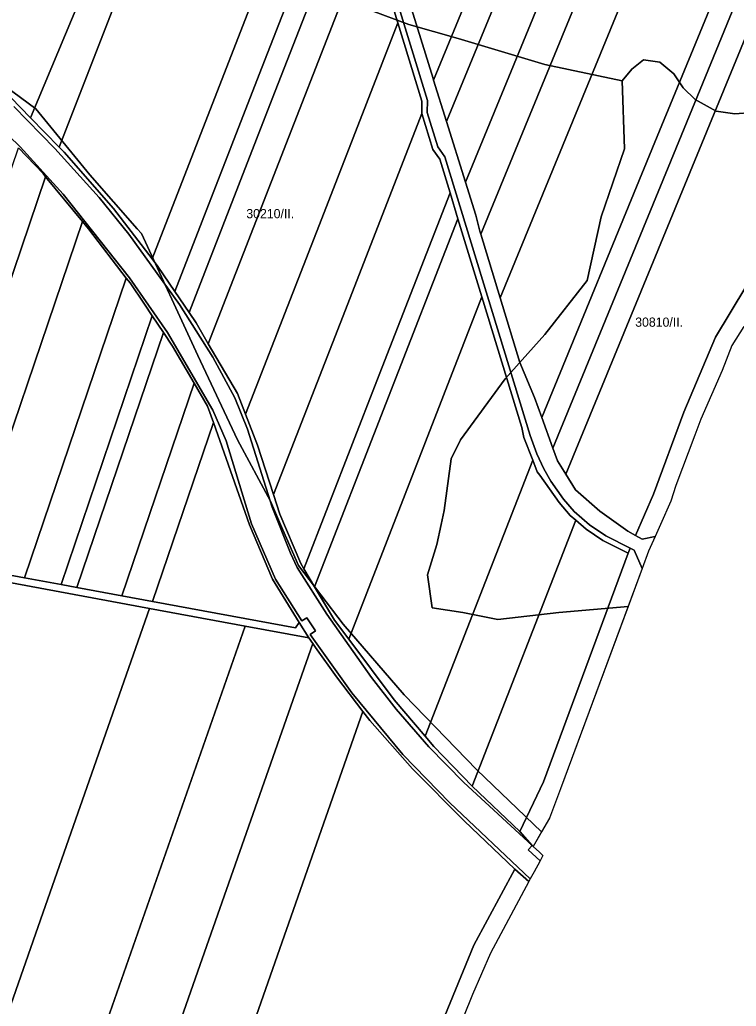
# Model space of a CAD drawing. Extents: x -545779 to -541342, y -1153413 to -1149956.
# Drawn here: x -543814 to -543424, y -1152262 to -1151726 of the extents above; entities that cross this region are included whole.
import ezdxf

# ---------------------------------------------------------------- set-up
doc = ezdxf.new("R2010")
doc.units = 0
for name, color, linetype in [('95560013', 7, 'Continuous'), ('95610013', 7, 'Continuous'), ('95640013', 7, 'Continuous'), ('95660013', 7, 'Continuous')]:
    doc.layers.add(name, color=color, linetype=linetype)

msp = doc.modelspace()

# ---------------------------------------------------------------- linework, layer by layer
at = {"layer": '95560013'}
for points in [[(-543540.88, -1151641.8), (-543588.85, -1151758.53), (-543589.15, -1151757.56), (-543606.61, -1151700.87), (-543565.52, -1151600.89), (-543524.44, -1151500.91), (-543519.6, -1151502.7), (-543506.97, -1151511.62), (-543492.9, -1151525.06)], [(-543482.25, -1151538.53), (-543532.06, -1151659.72), (-543581.86, -1151780.91), (-543588.85, -1151758.53), (-543540.88, -1151641.8), (-543492.9, -1151525.06)], [(-543571.54, -1151813.98), (-543581.86, -1151780.91), (-543532.06, -1151659.72), (-543482.25, -1151538.53), (-543466.34, -1151558.01), (-543518.94, -1151685.99)], [(-543466.34, -1151558.01), (-543453.25, -1151574.82), (-543508.2, -1151708.53), (-543563.15, -1151842.24), (-543563.68, -1151840.49), (-543565.94, -1151831.89), (-543571.54, -1151813.98), (-543518.94, -1151685.99)], [(-543744.51, -1151626.74), (-543743.07, -1151623.2), (-543727.55, -1151587.41), (-543724.37, -1151579.78), (-543720.4, -1151570.58), (-543719.77, -1151569.13), (-543706.77, -1151574.74), (-543749.64, -1151684.78), (-543792.5, -1151794.83), (-543808.08, -1151778.88)], [(-543741.95, -1151855.55), (-543762.98, -1151828.24), (-543789.76, -1151797.63), (-543792.5, -1151794.83), (-543749.64, -1151684.78), (-543706.77, -1151574.74), (-543695.14, -1151579.76), (-543677.64, -1151587.49), (-543662.32, -1151598.44), (-543650.77, -1151612.28), (-543648.69, -1151616.13), (-543695.32, -1151735.84)], [(-543552.58, -1151876.88), (-543563.15, -1151842.24), (-543508.2, -1151708.53), (-543453.25, -1151574.82), (-543448.01, -1151580.83), (-543441.65, -1151584.81), (-543427.65, -1151571.22), (-543427.2, -1151571.8), (-543489.89, -1151724.34)], [(-543418.53, -1151627.26), (-543406.97, -1151642.49), (-543468.49, -1151792.18), (-543530.01, -1151941.87), (-543533.97, -1151930.97), (-543541.88, -1151911.96), (-543552.58, -1151876.88), (-543489.89, -1151724.34), (-543427.2, -1151571.8), (-543402.91, -1151604.4)], [(-543773.4, -1151614.36), (-543759.65, -1151620.27), (-543750.15, -1151624.4), (-543744.51, -1151626.74), (-543808.08, -1151778.88), (-543818.82, -1151767.88), (-543849.25, -1151741.95), (-543857.35, -1151737.01), (-543800.95, -1151602.46), (-543787.28, -1151608.34)], [(-543695.32, -1151735.84), (-543648.69, -1151616.13), (-543641.79, -1151628.89), (-543637.69, -1151637.4), (-543683.63, -1151755.34), (-543729.57, -1151873.29), (-543738.74, -1151859.72), (-543741.95, -1151855.55)], [(-543683.63, -1151755.34), (-543637.69, -1151637.4), (-543633.38, -1151646.34), (-543631.4, -1151652.63), (-543676.61, -1151768.7), (-543721.82, -1151884.77), (-543729.57, -1151873.29)], [(-543398.65, -1151653.46), (-543461.32, -1151805.95), (-543523.99, -1151958.44), (-543530.01, -1151941.87), (-543468.49, -1151792.18), (-543406.97, -1151642.49)], [(-543631.4, -1151652.63), (-543623.77, -1151676.81), (-543667.58, -1151789.26), (-543711.38, -1151901.72), (-543718.05, -1151890.35), (-543721.82, -1151884.77), (-543676.61, -1151768.7)], [(-543521.45, -1151965.43), (-543523.99, -1151958.44), (-543461.32, -1151805.95), (-543398.65, -1151653.46), (-543390.07, -1151664.07), (-543453.49, -1151818.38), (-543516.9, -1151972.68)], [(-543479.1, -1152005.99), (-543483.3, -1152003.71), (-543498.41, -1151992.69), (-543511.62, -1151981.09), (-543516.9, -1151972.68), (-543453.49, -1151818.38), (-543390.07, -1151664.07), (-543376.03, -1151681.34), (-543368.01, -1151696.98), (-543362.61, -1151713.54), (-543361.78, -1151720.51), (-543383.75, -1151768.25), (-543397.66, -1151804.81), (-543419.12, -1151870.85), (-543435.52, -1151898.22), (-543452.76, -1151939.02), (-543469.17, -1151983.54)], [(-543667.58, -1151789.26), (-543623.77, -1151676.81), (-543621.29, -1151684.66), (-543608.23, -1151727.3), (-543649.67, -1151833.67), (-543691.1, -1151940.05), (-543695.44, -1151928.88), (-543711.38, -1151901.72)], [(-543608.23, -1151727.3), (-543595.18, -1151769.89), (-543595.28, -1151776.41), (-543595.23, -1151776.56), (-543635.58, -1151880.14), (-543675.92, -1151983.71), (-543684.57, -1151956.85), (-543691.1, -1151940.05), (-543649.67, -1151833.67)], [(-543595.23, -1151776.56), (-543589.24, -1151796.12), (-543585.51, -1151801.47), (-543579.9, -1151819.78), (-543619.68, -1151921.91), (-543659.46, -1152024.02), (-543661.13, -1152021.21), (-543672.46, -1151994.45), (-543675.92, -1151983.71), (-543635.58, -1151880.14)], [(-543835.09, -1151914.54), (-543870.28, -1152018.12), (-543889.21, -1152014.63), (-543851.95, -1151904.97), (-543814.68, -1151795.28), (-543801.27, -1151809.3), (-543799.9, -1151810.96)], [(-543779.82, -1151835.4), (-543843.57, -1152023.05), (-543870.28, -1152018.12), (-543835.09, -1151914.54), (-543799.9, -1151810.96)], [(-543619.68, -1151921.91), (-543579.9, -1151819.78), (-543575.59, -1151833.86), (-543614.56, -1151933.92), (-543653.53, -1152033.97), (-543659.46, -1152024.02)], [(-543776.57, -1151839.36), (-543755.96, -1151866.05), (-543811.31, -1152028.99), (-543843.57, -1152023.05), (-543779.82, -1151835.4)], [(-543642.79, -1152052.02), (-543653.53, -1152033.97), (-543614.56, -1151933.92), (-543575.59, -1151833.86), (-543562.58, -1151876.34), (-543635.03, -1152062.35)], [(-543753.93, -1151868.68), (-543746.14, -1151880.29), (-543741.85, -1151886.67), (-543791.45, -1152032.66), (-543811.31, -1152028.99), (-543755.96, -1151866.05)], [(-543534.95, -1151965.03), (-543593.42, -1152115.14), (-543610.22, -1152095.38), (-543635.03, -1152062.35), (-543562.58, -1151876.34), (-543540.86, -1151947.22), (-543539.72, -1151952.78)], [(-543735.78, -1151895.71), (-543782.84, -1152034.25), (-543791.45, -1152032.66), (-543741.85, -1151886.67)], [(-543730.91, -1151903.16), (-543719.11, -1151923.19), (-543758.37, -1152038.75), (-543782.84, -1152034.25), (-543735.78, -1151895.71)], [(-543711.73, -1151935.7), (-543708.6, -1151944.53), (-543741.66, -1152041.84), (-543758.37, -1152038.75), (-543719.11, -1151923.19)], [(-543520.63, -1151988.01), (-543514.55, -1151995.07), (-543511.5, -1151997.67), (-543567.8, -1152142.23), (-543588.76, -1152120.62), (-543593.42, -1152115.14), (-543534.95, -1151965.03), (-543532.44, -1151971.47), (-543531.08, -1151973.21)], [(-543567.8, -1152142.23), (-543511.5, -1151997.67), (-543505.84, -1152002.5), (-543496.73, -1152008.76), (-543482.99, -1152015.56), (-543529.07, -1152139.83), (-543541.94, -1152166.89)], [(-543856.48, -1152368.44), (-543883.11, -1152347.05), (-543969.58, -1152283.87), (-543978.75, -1152278.28), (-543933.3, -1152148.6), (-543887.85, -1152018.93), (-543743.35, -1152045.66), (-543799.91, -1152207.03)], [(-543856.48, -1152368.44), (-543799.91, -1152207.03), (-543743.35, -1152045.66), (-543691.28, -1152055.3), (-543752.24, -1152229.24), (-543813.2, -1152403.19)], [(-543752.24, -1152229.24), (-543691.28, -1152055.3), (-543656.75, -1152061.68), (-543654.59, -1152064.69), (-543718.28, -1152246.42), (-543782, -1152428.23), (-543813.2, -1152403.19)], [(-543782, -1152428.23), (-543718.28, -1152246.42), (-543654.59, -1152064.69), (-543652.99, -1152066.92), (-543641.63, -1152082.76), (-543627.26, -1152101.67), (-543688.93, -1152277.63), (-543750.56, -1152453.48)], [(-543566.98, -1152228.72), (-543618.4, -1152353.99), (-543643.99, -1152433.54), (-543671, -1152517.36), (-543750.56, -1152453.48), (-543688.93, -1152277.63), (-543627.26, -1152101.67), (-543623.6, -1152106.48), (-543600.39, -1152132.9), (-543572.16, -1152161.1), (-543544.74, -1152187.28)]]:
    msp.add_lwpolyline(points, close=True, dxfattribs=at)
at = {"layer": '95610013'}
msp.add_lwpolyline([(-543741.66, -1152041.84), (-543708.6, -1151944.53), (-543688.91, -1152000.16), (-543676.4, -1152029.69), (-543661.89, -1152053.31), (-543663.87, -1152056.18)], close=True, dxfattribs=at)
at = {"layer": '95640013'}
for points in [[(-543618.43, -1151683.78), (-543592.18, -1151769.46), (-543592.27, -1151775.98), (-543586.51, -1151794.79), (-543582.78, -1151800.14), (-543536.37, -1151951.65), (-543532.62, -1151961.53), (-543528.93, -1151969.7), (-543525.16, -1151976.39), (-543518.26, -1151986.16), (-543512.42, -1151992.94), (-543504.02, -1152000.12), (-543495.2, -1152006.17), (-543482.01, -1152012.9), (-543482.99, -1152015.56), (-543496.73, -1152008.76), (-543505.84, -1152002.5), (-543511.5, -1151997.67), (-543514.55, -1151995.07), (-543520.63, -1151988.01), (-543531.08, -1151973.21), (-543532.44, -1151971.47), (-543534.95, -1151965.03), (-543539.72, -1151952.78), (-543540.86, -1151947.22), (-543562.58, -1151876.34), (-543575.59, -1151833.86), (-543579.9, -1151819.78), (-543585.51, -1151801.47), (-543589.24, -1151796.12), (-543595.23, -1151776.56), (-543595.28, -1151776.41), (-543595.18, -1151769.89), (-543608.23, -1151727.3), (-543621.29, -1151684.66)], [(-543606.61, -1151700.87), (-543589.15, -1151757.56), (-543588.85, -1151758.53), (-543581.86, -1151780.91), (-543571.54, -1151813.98), (-543565.94, -1151831.89), (-543563.68, -1151840.49), (-543563.15, -1151842.24), (-543552.58, -1151876.88), (-543541.88, -1151911.96), (-543533.97, -1151930.97), (-543530.01, -1151941.87), (-543523.99, -1151958.44), (-543521.45, -1151965.43), (-543516.9, -1151972.68), (-543511.62, -1151981.09), (-543498.41, -1151992.69), (-543483.3, -1152003.71), (-543479.1, -1152005.99), (-543475.35, -1152008.02), (-543468.38, -1152006.45), (-543471.94, -1152014.51), (-543475.46, -1152023.99), (-543479.81, -1152014.01), (-543482.01, -1152012.9), (-543495.2, -1152006.17), (-543504.02, -1152000.12), (-543512.42, -1151992.94), (-543518.26, -1151986.16), (-543525.16, -1151976.39), (-543528.93, -1151969.7), (-543532.62, -1151961.53), (-543536.37, -1151951.65), (-543582.78, -1151800.14), (-543586.51, -1151794.79), (-543592.27, -1151775.98), (-543592.18, -1151769.46), (-543618.43, -1151683.78)], [(-543818.82, -1151767.88), (-543808.08, -1151778.88), (-543792.5, -1151794.83), (-543789.76, -1151797.63), (-543762.98, -1151828.24), (-543741.95, -1151855.55), (-543738.74, -1151859.72), (-543729.57, -1151873.29), (-543721.82, -1151884.77), (-543718.05, -1151890.35), (-543711.38, -1151901.72), (-543695.44, -1151928.88), (-543691.1, -1151940.05), (-543684.57, -1151956.85), (-543675.92, -1151983.71), (-543672.46, -1151994.45), (-543661.13, -1152021.21), (-543659.46, -1152024.02), (-543653.53, -1152033.97), (-543642.79, -1152052.02), (-543635.03, -1152062.35), (-543610.22, -1152095.38), (-543593.42, -1152115.14), (-543588.76, -1152120.62), (-543567.8, -1152142.23), (-543541.94, -1152166.89), (-543535.22, -1152174.49), (-543572.44, -1152140.22), (-543591.49, -1152120.83), (-543609.23, -1152100.37), (-543622.69, -1152083.08), (-543646.83, -1152048.74), (-543663.08, -1152023.39), (-543666.75, -1152015.54), (-543676.73, -1151990.52), (-543690, -1151948.26), (-543696.99, -1151931.24), (-543708.91, -1151909.1), (-543727.1, -1151880.35), (-543754.57, -1151842.26), (-543770.77, -1151822.23), (-543794.91, -1151795.61), (-543817.09, -1151772.85)], [(-543817.09, -1151772.85), (-543794.91, -1151795.61), (-543770.77, -1151822.23), (-543754.57, -1151842.26), (-543727.1, -1151880.35), (-543708.91, -1151909.1), (-543696.99, -1151931.24), (-543690, -1151948.26), (-543676.73, -1151990.52), (-543666.75, -1152015.54), (-543663.08, -1152023.39), (-543646.83, -1152048.74), (-543622.69, -1152083.08), (-543609.23, -1152100.37), (-543591.49, -1152120.83), (-543572.44, -1152140.22), (-543535.22, -1152174.49), (-543537.34, -1152176.76), (-543530.96, -1152182.76), (-543531.16, -1152183.13), (-543534.24, -1152188.85), (-543536.3, -1152192.69), (-543580.1, -1152151.37), (-543605.56, -1152125.07), (-543633.39, -1152091.58), (-543656.05, -1152059.81), (-543653.16, -1152057.74), (-543657.87, -1152050.76), (-543660.53, -1152052.45), (-543674.81, -1152029.65), (-543687.85, -1151999.6), (-543701.63, -1151954.51), (-543708.83, -1151937.79), (-543733.65, -1151895.72), (-543754.19, -1151865.97), (-543790.27, -1151820.39), (-543813.77, -1151794.69), (-543831.95, -1151777.22)], [(-543831.95, -1151777.22), (-543813.77, -1151794.69), (-543790.27, -1151820.39), (-543754.19, -1151865.97), (-543733.65, -1151895.72), (-543708.83, -1151937.79), (-543701.63, -1151954.51), (-543687.85, -1151999.6), (-543674.81, -1152029.65), (-543660.53, -1152052.45), (-543657.87, -1152050.76), (-543653.16, -1152057.74), (-543656.05, -1152059.81), (-543633.39, -1152091.58), (-543605.56, -1152125.07), (-543580.1, -1152151.37), (-543536.3, -1152192.69), (-543536.99, -1152193.98), (-543544.74, -1152187.28), (-543572.16, -1152161.1), (-543600.39, -1152132.9), (-543623.6, -1152106.48), (-543627.26, -1152101.67), (-543641.63, -1152082.76), (-543652.99, -1152066.92), (-543654.59, -1152064.69), (-543656.75, -1152061.68), (-543661.89, -1152053.31), (-543676.4, -1152029.69), (-543688.91, -1152000.16), (-543708.6, -1151944.53), (-543711.73, -1151935.7), (-543719.11, -1151923.19), (-543730.91, -1151903.16), (-543735.78, -1151895.71), (-543741.85, -1151886.67), (-543746.14, -1151880.29), (-543753.93, -1151868.68), (-543755.96, -1151866.05), (-543776.57, -1151839.36), (-543779.82, -1151835.4), (-543799.9, -1151810.96), (-543801.27, -1151809.3), (-543814.68, -1151795.28)], [(-543420.11, -1151892.3), (-543426.58, -1151902.76), (-543431.92, -1151916.35), (-543443.46, -1151942.7), (-543446.79, -1151951.52), (-543457.05, -1151978.72), (-543459.9, -1151987.3), (-543465.52, -1152000), (-543468.38, -1152006.45), (-543475.35, -1152008.02), (-543479.1, -1152005.99), (-543469.17, -1151983.54), (-543452.76, -1151939.02), (-543435.52, -1151898.22), (-543419.12, -1151870.85)], [(-543618.4, -1152353.99), (-543566.98, -1152228.72), (-543544.74, -1152187.28), (-543536.99, -1152193.98), (-543557.92, -1152232.99), (-543567.63, -1152255.49), (-543591.75, -1152315.33)]]:
    msp.add_lwpolyline(points, dxfattribs=at)
for points in [[(-543843.57, -1152023.05), (-543811.31, -1152028.99), (-543791.45, -1152032.66), (-543782.84, -1152034.25), (-543758.37, -1152038.75), (-543741.66, -1152041.84), (-543663.87, -1152056.18), (-543661.89, -1152053.31), (-543656.75, -1152061.68), (-543691.28, -1152055.3), (-543743.35, -1152045.66), (-543887.85, -1152018.93), (-543927.33, -1152011.63), (-543932.62, -1152014.61), (-543928.86, -1152003.9), (-543926.06, -1152007.84), (-543911.23, -1152010.57), (-543889.21, -1152014.63), (-543870.28, -1152018.12)], [(-543482.99, -1152015.56), (-543482.01, -1152012.9), (-543479.81, -1152014.01), (-543475.46, -1152023.99), (-543519.85, -1152143.72), (-543525.76, -1152159.65), (-543534.74, -1152175.03), (-543535.22, -1152174.49), (-543541.94, -1152166.89), (-543529.07, -1152139.83)], [(-543530.96, -1152182.76), (-543537.34, -1152176.76), (-543535.22, -1152174.49), (-543534.74, -1152175.03), (-543531.33, -1152178.12), (-543529.41, -1152179.86)]]:
    msp.add_lwpolyline(points, close=True, dxfattribs=at)
at = {"layer": '95660013'}
for points in [[(-543622.739, -1151720.567), (-543602.322, -1151728.223), (-543575.528, -1151735.879), (-543528.318, -1151749.914), (-543486.21, -1151758.846), (-543484.934, -1151795.849), (-543497.693, -1151832.852), (-543505.349, -1151867.303), (-543528.318, -1151896.651), (-543550.009, -1151920.894), (-543574.252, -1151954.069), (-543579.355, -1151964.277), (-543583.184, -1151992.348), (-543584.767, -1152000), (-543587.011, -1152010.85), (-543592.116, -1152027.437), (-543589.564, -1152045.301), (-543572.976, -1152047.853), (-543553.835, -1152051.68), (-543520.662, -1152047.853), (-543483.078, -1152044.537), (-543519.85, -1152143.72), (-543525.76, -1152159.65), (-543530.127, -1152167.129), (-543565.32, -1152133.342), (-543604.875, -1152092.511), (-543638.05, -1152054.232), (-543662.294, -1152022.333), (-543672.039, -1152000), (-543677.605, -1151987.244), (-543695.469, -1151954.069), (-543717.16, -1151908.134), (-543747.783, -1151841.784), (-543750, -1151839.266), (-543775.855, -1151809.885), (-543805.202, -1151774.158), (-543834.548, -1151752.466)], [(-543405.825, -1151775.434), (-543424.963, -1151776.71), (-543435.171, -1151775.434), (-543446.656, -1151769.054), (-543453.035, -1151762.674), (-543458.138, -1151755.018), (-543465.794, -1151748.638), (-543474.726, -1151747.362), (-543481.107, -1151752.466), (-543486.21, -1151758.846), (-543528.318, -1151749.914), (-543575.528, -1151735.879), (-543602.322, -1151728.223), (-543622.739, -1151720.567)], [(-543420.11, -1151892.3), (-543426.58, -1151902.76), (-543431.92, -1151916.35), (-543443.46, -1151942.7), (-543446.79, -1151951.52), (-543457.05, -1151978.72), (-543459.9, -1151987.3), (-543465.52, -1152000), (-543468.38, -1152006.45), (-543471.94, -1152014.51), (-543475.46, -1152023.99), (-543483.078, -1152044.537), (-543520.662, -1152047.853), (-543553.835, -1152051.68), (-543572.976, -1152047.853), (-543589.564, -1152045.301), (-543592.116, -1152027.437), (-543587.011, -1152010.85), (-543584.767, -1152000), (-543583.184, -1151992.348), (-543579.355, -1151964.277), (-543574.252, -1151954.069), (-543550.009, -1151920.894), (-543528.318, -1151896.651), (-543505.349, -1151867.303), (-543497.693, -1151832.852), (-543484.934, -1151795.849), (-543486.21, -1151758.846), (-543481.107, -1151752.466), (-543474.726, -1151747.362), (-543465.794, -1151748.638), (-543458.138, -1151755.018), (-543453.035, -1151762.674), (-543446.656, -1151769.054), (-543435.171, -1151775.434), (-543424.963, -1151776.71), (-543405.825, -1151775.434)], [(-543834.548, -1151752.466), (-543805.202, -1151774.158), (-543775.855, -1151809.885), (-543750, -1151839.266), (-543747.783, -1151841.784), (-543717.16, -1151908.134), (-543695.469, -1151954.069), (-543677.605, -1151987.244), (-543672.039, -1152000), (-543662.294, -1152022.333), (-543638.05, -1152054.232), (-543604.875, -1152092.511), (-543565.32, -1152133.342), (-543530.127, -1152167.129), (-543534.74, -1152175.03), (-543531.33, -1152178.12), (-543529.41, -1152179.86), (-543530.96, -1152182.76), (-543531.16, -1152183.13), (-543534.24, -1152188.85), (-543536.3, -1152192.69), (-543536.99, -1152193.98), (-543557.92, -1152232.99), (-543567.63, -1152255.49), (-543591.75, -1152315.33)]]:
    msp.add_lwpolyline(points, dxfattribs=at)

# ---------------------------------------------------------------- texts
for s, rotation, p in [('30210/II.', 0, (-543690.712, -1151833.546)), ('30810/II.', 360, (-543479.203, -1151892.514))]:
    msp.add_text(s, height=5, rotation=rotation, dxfattribs=at).set_placement(p)

doc.saveas('drawing.dxf')
